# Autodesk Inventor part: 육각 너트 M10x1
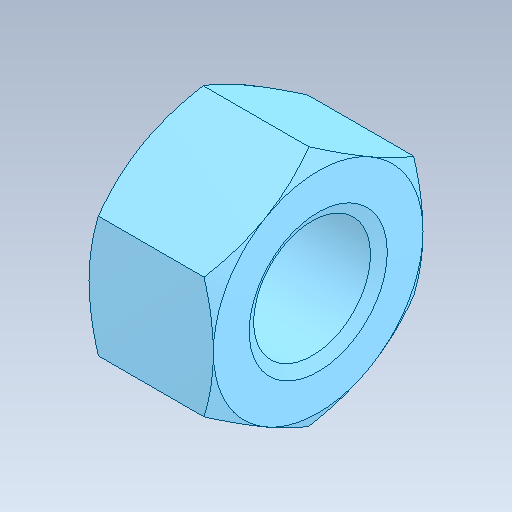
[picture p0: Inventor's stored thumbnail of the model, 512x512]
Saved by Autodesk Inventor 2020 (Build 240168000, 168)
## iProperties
Created: 2024-08
Part Number: 육각 너트 M10x1
Material: 강철, 연강
Description: 6각 너트 및 6각 가는 너트
Document SubType Name: Modeling
Designer: oem
Density: 7.85 g/cm^3
Appearance: 기본값
Author: jhkim
Sending System: Autodesk Inventor 2025
Preprocessor: ST-DEVELOPER v20
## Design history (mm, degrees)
node "육각 너트 M10x11"
node "솔리드1"
body "Solid1"
